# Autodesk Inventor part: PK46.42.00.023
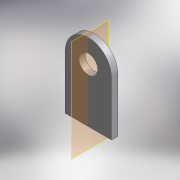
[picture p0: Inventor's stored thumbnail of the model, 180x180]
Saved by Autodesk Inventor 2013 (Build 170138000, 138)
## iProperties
Shininess: 25.0
Length Units: 11269
Angle Units: 11279
Time Units: 11290
Mass Units: 11283
Length Display Precision: 3
Angle Display Precision: 2
Created: 2001-08
Part Number: PK46.42.00.023
Material: Steel, Mild
Document SubType Name: Modeling
Designer: SOleg
Density: 7.86 g/cm^3
Mass: 40.568 g
Surface Area: 33.1996 cm^2
Volume: 5.16133 cm^3
Density: 0.0
Volumn: 0.0
Area: 0.0
PropertySet Name: Model Information
Control State: 0
Master: False
Checked Out: True
Checked Out Date: 2008-10-15
Last Check In Date: 2008-10-15
Author: SOleg
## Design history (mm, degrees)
node "ExtrusionBlind1" dims "d4" = 4, "d5" = 0
  sketch "Sketch1"
    geometry: L1 (258, 284)-(258, 249); L2 (258, 249)-(228, 249); L3 (228, 284)-(228, 249); A1 r 15 centre (243, 284) between (258, 284) and (228, 284)
    constraints: 6 end point, 2 point on circle, 2 tangent, 2 vertical, 1 centre point, 1 horizontal, 1 other
    dimensions: "d1" = 15 radius of A1; "d3" = 35 vertical distance of L1.end A1.centre
node "Hole1" dims "d7" = 12, "d8" = 4, "d9" = 2, "d10" = 60 deg, "d11" = 8, "d12" = 118 deg
  sketch "Sketch2"
    geometry: A1 r 15 centre (243, 284) between (258, 284) and (228, 284) reference; 1 further point
workplane "Work Plane2"
body "Solid1"
other parameters: "d0" = 15 (derived), "d2" = 35 (derived), "d6" = 0
